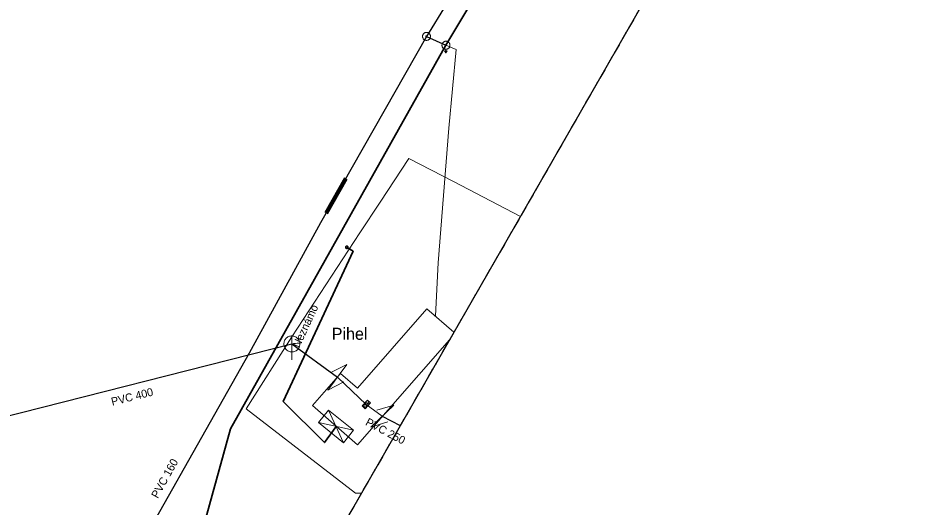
# Model space of a CAD drawing. Extents: x -724358 to -723714, y -973310 to -972026.
# Drawn here: x -724124.3 to -724013.1, y -972967.1 to -972905.9 of the extents above; entities that cross this region are included whole.
import ezdxf

# ---------------------------------------------------------------- set-up
doc = ezdxf.new("R2010")
doc.units = 0
doc.header["$LTSCALE"] = 0.4
doc.linetypes.add('MEDIUM_DASHED', pattern=[4.5, 3, -1.5])
for name, color, linetype, lineweight in [('1', 7, 'Continuous', 13), ('11', 7, 'Continuous', 13), ('13', 7, 'Continuous', 13), ('14', 7, 'Continuous', 13), ('16', 7, 'Continuous', 13), ('17', 7, 'Continuous', 25), ('19', 7, 'Continuous', 13), ('22', 7, 'Continuous', 13), ('23', 7, 'Continuous', 13), ('3', 7, 'Continuous', 106), ('31', 7, 'Continuous', 13), ('47', 7, 'Continuous', 13), ('6', 7, 'Continuous', 13)]:
    doc.layers.add(name, color=color, linetype=linetype, lineweight=lineweight)

msp = doc.modelspace()

# ---------------------------------------------------------------- linework, layer by layer
at = {"layer": '1', "linetype": 'MEDIUM_DASHED', "lineweight": 25}
msp.add_lwpolyline([(-723809.944, -972026.35), (-723713.647, -972034.723), (-723734.581, -972361.295), (-724123.956, -973039.561), (-724241.187, -973309.611), (-724358.418, -973148.418), (-723860.186, -972315.24)], close=True, dxfattribs=at)
at = {"layer": '1', "lineweight": 25}
msp.add_lwpolyline([(-724019.563, -972857.716), (-724123.956, -973039.561)], dxfattribs=at)
at = {"layer": '1'}
for points in [[(-724081.332, -972965.313), (-724082.059, -972965.32), (-724095.76, -972954.77), (-724090.039, -972945.76), (-724081.55, -972932.739), (-724079, -972928.899), (-724075.399, -972923.469), (-724069.829, -972926.309), (-724061.459, -972930.695)], [(-724070.323, -972946.136), (-724081.809, -972959.28), (-724087.44, -972954.329), (-724083.96, -972950.34), (-724081.829, -972952.19), (-724073.16, -972942.25), (-724069.773, -972945.178)]]:
    msp.add_lwpolyline(points, close=True, dxfattribs=at)
at = {"layer": '11', "lineweight": 35}
msp.add_lwpolyline([(-724083.01, -972934.66), (-724082.383, -972935.046), (-724088.224, -972947.692), (-724091.097, -972953.843), (-724085.966, -972958.983), (-724084.485, -972956.971)], dxfattribs=at)
at = {"layer": '13'}
msp.add_lwpolyline([(-724070.768, -972909.289), (-724069.511, -972909.816), (-724070.399, -972919.66), (-724071.763, -972936.504), (-724072.059, -972943.146)], dxfattribs=at)
at = {"layer": '14', "lineweight": 25}
msp.add_line((-724078.726, -972955.659), (-724076.472, -972956.847), dxfattribs=at)
msp.add_lwpolyline([(-724199.68, -973042.18), (-724175.35, -972998.37), (-724168.649, -972968.05), (-724140.149, -972952.289), (-724129.112, -972956.537), (-724090.03, -972946.64), (-724084.339, -972950.81)], dxfattribs=at)
at = {"layer": '16'}
for p, q in [((-724084.339, -972950.81), (-724080.724, -972954.196)), ((-724080.724, -972954.196), (-724078.726, -972955.659))]:
    msp.add_line(p, q, dxfattribs=at)
at = {"layer": '17', "lineweight": 35}
msp.add_line((-724070.768, -972909.289), (-724022.349, -972827.559), dxfattribs=at)
at = {"layer": '17'}
msp.add_line((-724073.199, -972908.18), (-724070.768, -972909.289), dxfattribs=at)
for points in [[(-724025.8, -972827.022), (-724033.14, -972840.629), (-724045.07, -972861.41), (-724063.359, -972892.16), (-724073.199, -972908.18)], [(-724073.199, -972908.18), (-724086.44, -972931.51), (-724095.37, -972947.8), (-724113.059, -972979.149), (-724115.579, -972986.14), (-724118.629, -972990.349)]]:
    msp.add_lwpolyline(points, dxfattribs=at)
at = {"layer": '17', "lineweight": 35}
msp.add_lwpolyline([(-724113.111, -973013.057), (-724097.71, -972957.24), (-724070.768, -972909.289)], dxfattribs=at)
at = {"layer": '19'}
for p, q in [((-724082.891, -972934.739), (-724083.009, -972934.66)), ((-724085.432, -972954.918), (-724083.594, -972959.006)), ((-724086.703, -972956.486), (-724082.323, -972957.438))]:
    msp.add_line(p, q, dxfattribs=at)
for points in [[(-724083.058, -972934.414), (-724083.074, -972934.404), (-724083.091, -972934.396), (-724083.108, -972934.391), (-724083.125, -972934.386), (-724083.143, -972934.384), (-724083.162, -972934.384), (-724083.181, -972934.385), (-724083.198, -972934.389), (-724083.217, -972934.394), (-724083.233, -972934.401), (-724083.251, -972934.41), (-724083.264, -972934.421), (-724083.279, -972934.434), (-724083.291, -972934.447), (-724083.304, -972934.462), (-724083.313, -972934.479), (-724083.32, -972934.495), (-724083.326, -972934.513), (-724083.331, -972934.53), (-724083.333, -972934.55), (-724083.334, -972934.567), (-724083.331, -972934.586), (-724083.328, -972934.604), (-724083.322, -972934.622), (-724083.314, -972934.639), (-724083.306, -972934.655), (-724083.296, -972934.671), (-724083.283, -972934.683), (-724083.27, -972934.697), (-724083.256, -972934.707), (-724083.239, -972934.717), (-724083.221, -972934.724), (-724083.205, -972934.732), (-724083.187, -972934.736), (-724083.167, -972934.738), (-724083.149, -972934.738), (-724083.131, -972934.737), (-724083.113, -972934.732), (-724083.095, -972934.727), (-724083.079, -972934.72), (-724083.062, -972934.711), (-724083.047, -972934.7), (-724083.033, -972934.688), (-724083.021, -972934.674), (-724083.009, -972934.66), (-724083, -972934.643), (-724082.992, -972934.627), (-724082.985, -972934.608), (-724082.981, -972934.591), (-724082.979, -972934.572), (-724082.979, -972934.554), (-724082.981, -972934.535), (-724082.984, -972934.518), (-724082.989, -972934.5), (-724082.996, -972934.483), (-724083.006, -972934.467), (-724083.017, -972934.452), (-724083.029, -972934.438), (-724083.043, -972934.425)], [(-724082.878, -972934.719), (-724082.879, -972934.718), (-724082.882, -972934.716), (-724082.885, -972934.717), (-724082.889, -972934.715), (-724082.89, -972934.716), (-724082.892, -972934.715), (-724082.895, -972934.716), (-724082.896, -972934.716), (-724082.899, -972934.717), (-724082.902, -972934.717), (-724082.903, -972934.719), (-724082.906, -972934.721), (-724082.908, -972934.721), (-724082.91, -972934.724), (-724082.911, -972934.726), (-724082.913, -972934.728), (-724082.914, -972934.73), (-724082.913, -972934.733), (-724082.914, -972934.736), (-724082.915, -972934.737), (-724082.915, -972934.74), (-724082.914, -972934.742), (-724082.915, -972934.745), (-724082.913, -972934.747), (-724082.912, -972934.749), (-724082.913, -972934.751), (-724082.91, -972934.754), (-724082.908, -972934.755), (-724082.906, -972934.758), (-724082.905, -972934.759), (-724082.902, -972934.761), (-724082.9, -972934.761), (-724082.899, -972934.761), (-724082.895, -972934.763), (-724082.893, -972934.762), (-724082.891, -972934.762), (-724082.889, -972934.762), (-724082.885, -972934.761), (-724082.884, -972934.761), (-724082.881, -972934.76), (-724082.879, -972934.76), (-724082.876, -972934.758), (-724082.875, -972934.756), (-724082.874, -972934.754), (-724082.872, -972934.752), (-724082.871, -972934.75), (-724082.869, -972934.748), (-724082.868, -972934.746), (-724082.867, -972934.743), (-724082.868, -972934.74), (-724082.868, -972934.737), (-724082.867, -972934.736), (-724082.869, -972934.733), (-724082.87, -972934.73), (-724082.871, -972934.729), (-724082.871, -972934.727), (-724082.874, -972934.724), (-724082.874, -972934.722), (-724082.875, -972934.721)], [(-724082.885, -972934.729), (-724082.886, -972934.728), (-724082.886, -972934.728), (-724082.888, -972934.727), (-724082.889, -972934.726), (-724082.891, -972934.727), (-724082.891, -972934.727), (-724082.894, -972934.726), (-724082.894, -972934.727), (-724082.896, -972934.727), (-724082.896, -972934.727), (-724082.898, -972934.728), (-724082.899, -972934.729), (-724082.9, -972934.731), (-724082.9, -972934.731), (-724082.901, -972934.732), (-724082.902, -972934.733), (-724082.903, -972934.735), (-724082.903, -972934.735), (-724082.904, -972934.736), (-724082.904, -972934.738), (-724082.904, -972934.739), (-724082.903, -972934.741), (-724082.903, -972934.741), (-724082.903, -972934.743), (-724082.903, -972934.743), (-724082.902, -972934.745), (-724082.901, -972934.746), (-724082.9, -972934.748), (-724082.9, -972934.748), (-724082.898, -972934.749), (-724082.897, -972934.749), (-724082.895, -972934.751), (-724082.895, -972934.75), (-724082.893, -972934.751), (-724082.892, -972934.751), (-724082.892, -972934.751), (-724082.889, -972934.75), (-724082.889, -972934.75), (-724082.887, -972934.75), (-724082.886, -972934.75), (-724082.885, -972934.749), (-724082.884, -972934.748), (-724082.884, -972934.748), (-724082.883, -972934.746), (-724082.882, -972934.745), (-724082.881, -972934.743), (-724082.881, -972934.743), (-724082.88, -972934.742), (-724082.879, -972934.741), (-724082.879, -972934.739), (-724082.879, -972934.739), (-724082.88, -972934.737), (-724082.88, -972934.736), (-724082.881, -972934.734), (-724082.881, -972934.734), (-724082.88, -972934.732), (-724082.882, -972934.731), (-724082.882, -972934.731), (-724082.884, -972934.73)], [(-724085.432, -972954.918), (-724082.323, -972957.438), (-724083.594, -972959.006), (-724086.703, -972956.486)]]:
    msp.add_lwpolyline(points, close=True, dxfattribs=at)
for points in [[(-724083.304, -972934.462), (-724083.134, -972934.632), (-724083.172, -972934.494), (-724083.009, -972934.66)], [(-724083.262, -972934.526), (-724083.304, -972934.462), (-724083.238, -972934.501)]]:
    msp.add_lwpolyline(points, dxfattribs=at)
at = {"layer": '22'}
msp.add_line((-724090.03, -972948.64), (-724090.029, -972945.64), dxfattribs=at)
msp.add_lwpolyline([(-724089.03, -972946.64), (-724089.035, -972946.531), (-724089.053, -972946.423), (-724089.083, -972946.317), (-724089.123, -972946.216), (-724089.175, -972946.119), (-724089.237, -972946.029), (-724089.309, -972945.946), (-724089.389, -972945.872), (-724089.477, -972945.806), (-724089.571, -972945.751), (-724089.671, -972945.706), (-724089.776, -972945.673), (-724089.883, -972945.651), (-724089.992, -972945.641), (-724090.102, -972945.643), (-724090.21, -972945.657), (-724090.317, -972945.682), (-724090.42, -972945.719), (-724090.518, -972945.768), (-724090.61, -972945.826), (-724090.696, -972945.895), (-724090.773, -972945.972), (-724090.842, -972946.058), (-724090.901, -972946.15), (-724090.949, -972946.248), (-724090.986, -972946.351), (-724091.012, -972946.458), (-724091.026, -972946.566), (-724091.029, -972946.676), (-724091.019, -972946.785), (-724090.998, -972946.892), (-724090.964, -972946.996), (-724090.92, -972947.096), (-724090.865, -972947.191), (-724090.799, -972947.279), (-724090.725, -972947.359), (-724090.642, -972947.431), (-724090.552, -972947.493), (-724090.456, -972947.545), (-724090.354, -972947.586), (-724090.249, -972947.616), (-724090.141, -972947.634), (-724090.031, -972947.64), (-724089.922, -972947.634), (-724089.814, -972947.616), (-724089.709, -972947.587), (-724089.607, -972947.546), (-724089.51, -972947.494), (-724089.42, -972947.432), (-724089.337, -972947.361), (-724089.262, -972947.281), (-724089.197, -972947.193), (-724089.141, -972947.099), (-724089.097, -972946.999), (-724089.063, -972946.895), (-724089.041, -972946.787), (-724089.031, -972946.678)], close=True, dxfattribs=at)
at = {"layer": '23'}
for p, q in [((-724070.796, -972910.245), (-724070.78, -972909.78)), ((-724070.953, -972909.992), (-724070.796, -972910.245)), ((-724070.638, -972910.026), (-724070.937, -972910.015)), ((-724070.656, -972910.053), (-724070.922, -972910.043)), ((-724070.675, -972910.075), (-724070.903, -972910.068)), ((-724070.693, -972910.098), (-724070.889, -972910.093)), ((-724070.709, -972910.122), (-724070.875, -972910.117)), ((-724070.726, -972910.149), (-724070.86, -972910.144)), ((-724070.743, -972910.172), (-724070.844, -972910.169)), ((-724070.763, -972910.195), (-724070.827, -972910.193)), ((-724070.779, -972910.222), (-724070.811, -972910.221)), ((-724070.623, -972910.003), (-724070.788, -972909.997))]:
    msp.add_line(p, q, dxfattribs=at)
msp.add_lwpolyline([(-724071.268, -972909.272), (-724071.266, -972909.324), (-724071.26, -972909.376), (-724071.249, -972909.427), (-724071.232, -972909.477), (-724071.21, -972909.525), (-724071.181, -972909.569), (-724071.15, -972909.61), (-724071.114, -972909.649), (-724071.076, -972909.684), (-724071.033, -972909.713), (-724070.986, -972909.739), (-724070.937, -972909.758), (-724070.889, -972909.774), (-724070.836, -972909.784), (-724070.784, -972909.788), (-724070.733, -972909.786), (-724070.681, -972909.781), (-724070.629, -972909.769), (-724070.581, -972909.753), (-724070.533, -972909.73), (-724070.488, -972909.702), (-724070.446, -972909.671), (-724070.406, -972909.635), (-724070.374, -972909.596), (-724070.343, -972909.553), (-724070.318, -972909.507), (-724070.298, -972909.459), (-724070.283, -972909.409), (-724070.273, -972909.357), (-724070.268, -972909.305), (-724070.27, -972909.253), (-724070.276, -972909.201), (-724070.287, -972909.15), (-724070.304, -972909.101), (-724070.327, -972909.053), (-724070.354, -972909.008), (-724070.385, -972908.966), (-724070.421, -972908.929), (-724070.461, -972908.894), (-724070.503, -972908.864), (-724070.55, -972908.838), (-724070.597, -972908.818), (-724070.648, -972908.803), (-724070.7, -972908.794), (-724070.752, -972908.789), (-724070.804, -972908.791), (-724070.855, -972908.797), (-724070.907, -972908.808), (-724070.956, -972908.824), (-724071.004, -972908.848), (-724071.048, -972908.874), (-724071.088, -972908.906), (-724071.127, -972908.941), (-724071.163, -972908.981), (-724071.193, -972909.024), (-724071.218, -972909.07), (-724071.238, -972909.118), (-724071.253, -972909.169), (-724071.264, -972909.22)], close=True, dxfattribs=at)
msp.add_lwpolyline([(-724070.796, -972910.245), (-724070.623, -972910.003), (-724070.953, -972909.992)], dxfattribs=at)
at = {"layer": '3'}
msp.add_line((-724083.278, -972925.938), (-724085.746, -972930.286), dxfattribs=at)
at = {"layer": '3', "lineweight": 100}
msp.add_line((-724083.278, -972925.938), (-724085.746, -972930.286), dxfattribs=at)
at = {"layer": '31'}
for points in [[(-724085.145, -972950.219), (-724083.156, -972949.197), (-724085.521, -972952.423), (-724083.532, -972951.401)], [(-724079.413, -972954.932), (-724077.273, -972954.285), (-724080.179, -972957.033), (-724078.039, -972956.385)]]:
    msp.add_lwpolyline(points, dxfattribs=at)
at = {"layer": '47'}
for points in [[(-724072.7, -972908.18), (-724072.703, -972908.128), (-724072.711, -972908.076), (-724072.725, -972908.026), (-724072.742, -972907.977), (-724072.767, -972907.93), (-724072.796, -972907.886), (-724072.828, -972907.846), (-724072.865, -972907.809), (-724072.906, -972907.776), (-724072.95, -972907.747), (-724072.997, -972907.723), (-724073.046, -972907.705), (-724073.095, -972907.691), (-724073.147, -972907.683), (-724073.2, -972907.68), (-724073.252, -972907.683), (-724073.304, -972907.691), (-724073.355, -972907.705), (-724073.402, -972907.723), (-724073.45, -972907.747), (-724073.494, -972907.776), (-724073.534, -972907.809), (-724073.571, -972907.846), (-724073.605, -972907.886), (-724073.632, -972907.93), (-724073.657, -972907.977), (-724073.676, -972908.026), (-724073.688, -972908.076), (-724073.696, -972908.128), (-724073.7, -972908.18), (-724073.696, -972908.232), (-724073.688, -972908.284), (-724073.676, -972908.335), (-724073.657, -972908.383), (-724073.632, -972908.43), (-724073.605, -972908.474), (-724073.571, -972908.515), (-724073.534, -972908.552), (-724073.494, -972908.585), (-724073.45, -972908.613), (-724073.402, -972908.637), (-724073.355, -972908.656), (-724073.304, -972908.669), (-724073.252, -972908.677), (-724073.2, -972908.68), (-724073.147, -972908.677), (-724073.095, -972908.669), (-724073.046, -972908.656), (-724072.997, -972908.637), (-724072.95, -972908.613), (-724072.906, -972908.585), (-724072.865, -972908.552), (-724072.828, -972908.515), (-724072.796, -972908.474), (-724072.767, -972908.43), (-724072.742, -972908.383), (-724072.725, -972908.335), (-724072.711, -972908.284), (-724072.703, -972908.232)], [(-724073.117, -972908.18), (-724073.117, -972908.171), (-724073.12, -972908.163), (-724073.122, -972908.155), (-724073.125, -972908.147), (-724073.129, -972908.139), (-724073.134, -972908.132), (-724073.139, -972908.125), (-724073.144, -972908.119), (-724073.152, -972908.114), (-724073.159, -972908.109), (-724073.166, -972908.105), (-724073.174, -972908.102), (-724073.183, -972908.1), (-724073.191, -972908.098), (-724073.2, -972908.098), (-724073.208, -972908.098), (-724073.217, -972908.1), (-724073.225, -972908.102), (-724073.233, -972908.105), (-724073.24, -972908.109), (-724073.247, -972908.114), (-724073.255, -972908.119), (-724073.261, -972908.125), (-724073.267, -972908.132), (-724073.271, -972908.139), (-724073.274, -972908.147), (-724073.277, -972908.155), (-724073.279, -972908.163), (-724073.282, -972908.171), (-724073.282, -972908.18), (-724073.282, -972908.189), (-724073.279, -972908.197), (-724073.277, -972908.205), (-724073.274, -972908.213), (-724073.271, -972908.221), (-724073.267, -972908.228), (-724073.261, -972908.235), (-724073.255, -972908.241), (-724073.247, -972908.247), (-724073.24, -972908.251), (-724073.233, -972908.255), (-724073.225, -972908.258), (-724073.217, -972908.26), (-724073.208, -972908.262), (-724073.2, -972908.262), (-724073.191, -972908.262), (-724073.183, -972908.26), (-724073.174, -972908.258), (-724073.166, -972908.255), (-724073.159, -972908.251), (-724073.152, -972908.247), (-724073.144, -972908.241), (-724073.139, -972908.235), (-724073.134, -972908.228), (-724073.129, -972908.221), (-724073.125, -972908.213), (-724073.122, -972908.205), (-724073.12, -972908.197), (-724073.117, -972908.189)]]:
    msp.add_lwpolyline(points, close=True, dxfattribs=at)
at = {"layer": '6'}
for p in [(-724080.73, -972953.962), (-724080.546, -972953.756)]:
    msp.add_line(p, (-724080.368, -972954.1), dxfattribs=at)
for points in [[(-724081.241, -972954.402), (-724080.575, -972953.656), (-724080.199, -972953.992), (-724080.864, -972954.739)], [(-724080.84, -972954.085), (-724080.852, -972954.121), (-724080.849, -972954.172), (-724080.836, -972954.21), (-724080.808, -972954.255), (-724080.744, -972954.312), (-724080.696, -972954.335), (-724080.655, -972954.345), (-724080.605, -972954.341), (-724080.57, -972954.326), (-724080.525, -972954.276), (-724080.514, -972954.239), (-724080.516, -972954.189), (-724080.534, -972954.153), (-724080.561, -972954.107), (-724080.625, -972954.05), (-724080.674, -972954.028), (-724080.71, -972954.016), (-724080.761, -972954.019), (-724080.795, -972954.035)]]:
    msp.add_lwpolyline(points, close=True, dxfattribs=at)
for points in [[(-724081.097, -972954.277), (-724081.036, -972954.275), (-724081.039, -972954.212)], [(-724080.873, -972954.251), (-724080.909, -972954.239), (-724080.96, -972954.242), (-724080.994, -972954.258), (-724081.039, -972954.308), (-724081.052, -972954.345), (-724081.048, -972954.395), (-724081.035, -972954.433), (-724081.008, -972954.479), (-724080.944, -972954.536), (-724080.895, -972954.558), (-724080.854, -972954.568), (-724080.805, -972954.565), (-724080.769, -972954.549), (-724080.724, -972954.499), (-724080.713, -972954.462), (-724080.715, -972954.412), (-724080.733, -972954.376)]]:
    msp.add_lwpolyline(points, dxfattribs=at)

# ---------------------------------------------------------------- texts
at = {"layer": '1'}
for s, rotation, p in [('Neznámo ', 65, (-724089.106, -972947.205)), ('PVC 400 ', 14, (-724112.476, -972954.371)), ('PVC 250 ', 332, (-724080.922, -972956.73)), ('PVC 160 ', 61, (-724106.792, -972966.038))]:
    msp.add_text(s, height=1, rotation=rotation, dxfattribs=at).set_placement(p)
msp.add_text('Pihel ', height=1.5, dxfattribs=at).set_placement((-724085.041, -972946.125))

doc.saveas('drawing.dxf')
